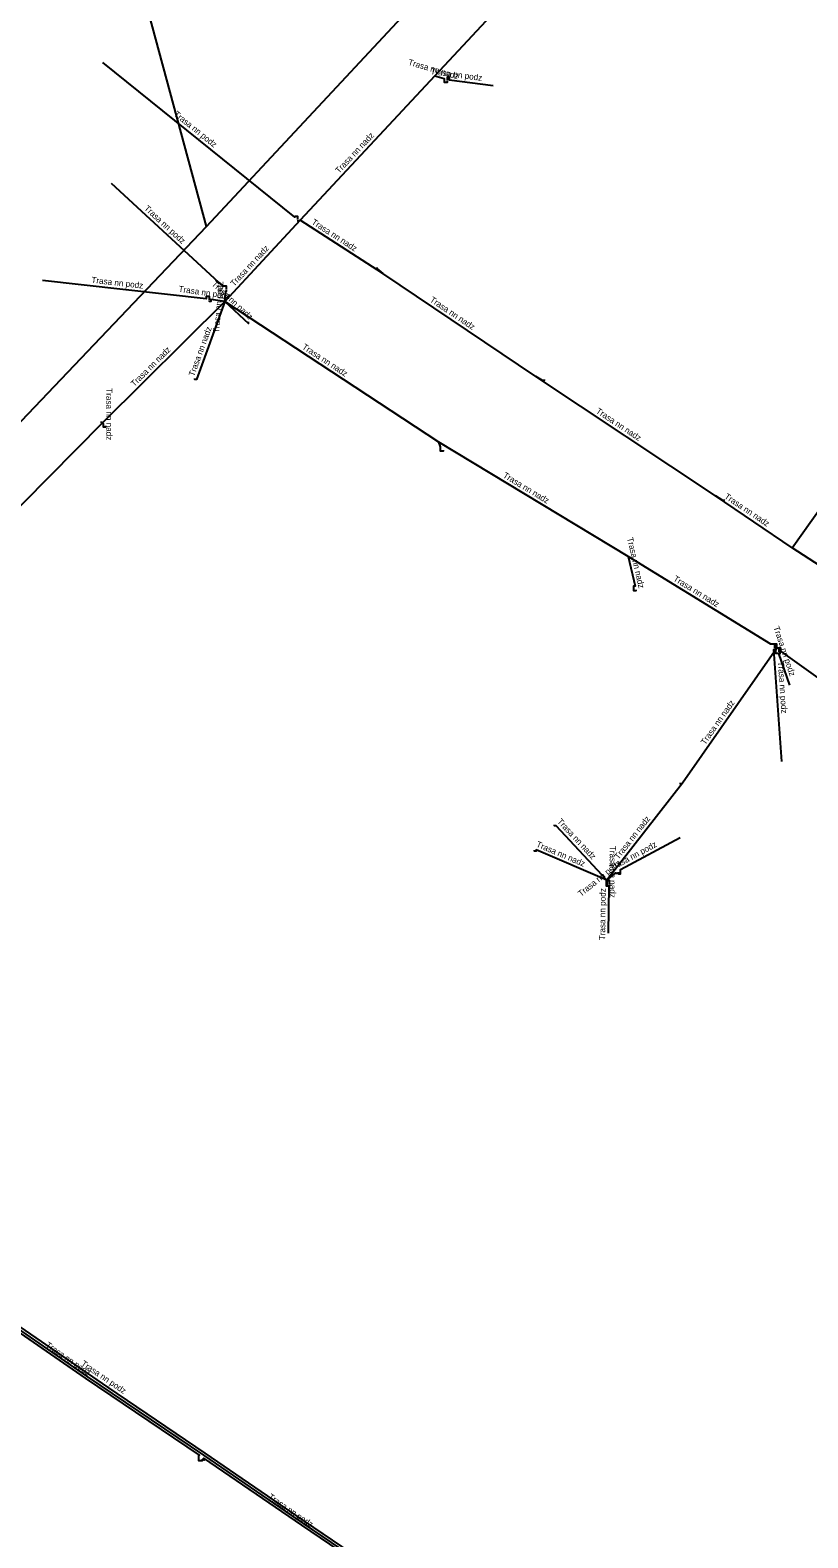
# Model space of a CAD drawing. Extents: x -742082 to -717476, y -1040737 to -1024597.
# Drawn here: x -736402.1 to -736274.4, y -1032679.3 to -1032431.7 of the extents above; entities that cross this region are included whole.
import ezdxf

# ---------------------------------------------------------------- set-up
doc = ezdxf.new("R2010")
doc.units = 0
for name, color, linetype in [('Level 13', 7, 'Continuous'), ('Level 14', 7, 'Continuous'), ('Level 15', 7, 'Continuous'), ('Level 20', 7, 'Continuous'), ('Level 24', 7, 'Continuous')]:
    doc.layers.add(name, color=color, linetype=linetype)

msp = doc.modelspace()

# ---------------------------------------------------------------- linework, layer by layer
at = {"layer": 'Level 13'}
for p, q in [((-736313.17, -1032415.01), (-736335.68, -1032439.22)), ((-736335.68, -1032439.22), (-736357.82, -1032462.91)), ((-736357.82, -1032462.91), (-736370.18, -1032476.28)), ((-736344.2, -1032471.7), (-736357.82, -1032462.91)), ((-736319.1, -1032488.6), (-736344.2, -1032471.7)), ((-736370.18, -1032476.28), (-736390.27, -1032496.22)), ((-736335, -1032499.4), (-736370.18, -1032476.28)), ((-736289.6, -1032508.2), (-736319.1, -1032488.6)), ((-736276.98, -1032516.71), (-736257.81, -1032489.67)), ((-736390.27, -1032496.22), (-736419.45, -1032525.69)), ((-736303.93, -1032518.14), (-736335, -1032499.4)), ((-736276.98, -1032516.71), (-736289.6, -1032508.2)), ((-736257.1, -1032529.7), (-736276.98, -1032516.71)), ((-736279.5, -1032533.2), (-736295.02, -1032555.39)), ((-736295.02, -1032555.39), (-736307.44, -1032571.28))]:
    msp.add_line(p, q, dxfattribs=at)
for points in [[(-736335.68, -1032439.22), (-736334.15, -1032439.67), (-736334.15, -1032440.26), (-736333.6, -1032440.26), (-736333.6, -1032440)], [(-736358.2, -1032462.9), (-736358.2, -1032463.06), (-736358.03, -1032463.06), (-736357.82, -1032462.91)], [(-736345.2, -1032470.7), (-736345.2, -1032470.86), (-736344.2, -1032471.7)], [(-736370.4, -1032476.1), (-736370.4, -1032476.27), (-736370.18, -1032476.28)], [(-736317.7, -1032489.1), (-736317.7, -1032489.26), (-736317.98, -1032489.26), (-736319.1, -1032488.6)], [(-736390.5, -1032496), (-736390.5, -1032496.16), (-736390.27, -1032496.22)], [(-736390.27, -1032496.22), (-736390.15, -1032496.29), (-736390.15, -1032496.86), (-736389.7, -1032496.86), (-736389.7, -1032496.7)], [(-736334.3, -1032500.7), (-736334.3, -1032500.86), (-736334.75, -1032500.86), (-736334.75, -1032500.15), (-736335, -1032499.4)], [(-736288.2, -1032508.8), (-736288.2, -1032508.96), (-736288.39, -1032508.96), (-736289.6, -1032508.2)], [(-736279.5, -1032533.2), (-736279.5, -1032532.57), (-736280.52, -1032532.57), (-736303.93, -1032518.14)], [(-736279.91, -1032533.24), (-736279.91, -1032533.4), (-736279.65, -1032533.4), (-736279.5, -1032533.2)], [(-736279.2, -1032533.9), (-736279.2, -1032534.06), (-736279.65, -1032534.06), (-736279.65, -1032533.61), (-736279.5, -1032533.2)], [(-736252.87, -1032552.27), (-736278.83, -1032533.68), (-736278.83, -1032533.2), (-736279.5, -1032533.2)], [(-736295.4, -1032555.3), (-736295.4, -1032555.46), (-736295.15, -1032555.46), (-736295.02, -1032555.39)], [(-736307.44, -1032571.28), (-736307.33, -1032571.45), (-736307.45, -1032571.45), (-736307.45, -1032572.16), (-736307, -1032572.16), (-736307, -1032572)]]:
    msp.add_lwpolyline(points, dxfattribs=at)
at = {"layer": 'Level 14'}
for points in [[(-736370.18, -1032476.28), (-736374.84, -1032489.11), (-736375.1, -1032489.11), (-736375.1, -1032488.9)], [(-736370.18, -1032476.28), (-736366.3, -1032479.88), (-736366.3, -1032479.6)], [(-736303.93, -1032518.14), (-736302.78, -1032523.05), (-736303.05, -1032523.05), (-736303.05, -1032523.76), (-736302.6, -1032523.76), (-736302.6, -1032523.6)], [(-736307.44, -1032571.28), (-736315.77, -1032562.36), (-736316, -1032562.36), (-736316, -1032562.2)], [(-736307.44, -1032571.28), (-736319.05, -1032566.35), (-736319.05, -1032566.56), (-736319.3, -1032566.56), (-736319.3, -1032566.4)]]:
    msp.add_lwpolyline(points, dxfattribs=at)
at = {"layer": 'Level 15'}
for points in [[(-736358.2, -1032462.79), (-736358.2, -1032462.34), (-736358.65, -1032462.34), (-736358.65, -1032462.42), (-736390.2, -1032437)], [(-736333.6, -1032439.89), (-736333.6, -1032439.45), (-736333.34, -1032439.45), (-736333.34, -1032439.85), (-736326.1, -1032440.8)], [(-736369.9, -1032474.29), (-736369.9, -1032473.75), (-736370.45, -1032473.75), (-736370.45, -1032473.79), (-736388.8, -1032456.9)], [(-736372.7, -1032475.99), (-736372.7, -1032475.45), (-736373.25, -1032475.45), (-736373.25, -1032475.85), (-736400.1, -1032472.8)], [(-736370.18, -1032476.28), (-736372.45, -1032475.95), (-736372.45, -1032476.26), (-736372.7, -1032476.26), (-736372.7, -1032476.1)], [(-736370.18, -1032476.28), (-736370.03, -1032474.56), (-736369.9, -1032474.56), (-736369.9, -1032474.4)], [(-736278.7, -1032551.8), (-736279.98, -1032533.4), (-736279.65, -1032533.4), (-736279.65, -1032532.69), (-736279.91, -1032532.69), (-736279.91, -1032532.74), (-736279.91, -1032533.13)], [(-736277.4, -1032539.3), (-736279.18, -1032534.06), (-736278.95, -1032534.06), (-736278.95, -1032533.35), (-736279.2, -1032533.35), (-736279.2, -1032533.79)], [(-736305.53, -1032570.01), (-736305.53, -1032570.27), (-736305.18, -1032570.27), (-736305.18, -1032569.57), (-736295.4, -1032564.3)], [(-736307.44, -1032571.28), (-736305.98, -1032570.1), (-736305.98, -1032570.16), (-736305.53, -1032570.16), (-736305.53, -1032570.01)], [(-736307, -1032571.89), (-736307, -1032571.35), (-736307.55, -1032571.35), (-736307.55, -1032572.26), (-736307.11, -1032572.26), (-736307.2, -1032580)], [(-736342.82, -1032687.29), (-736342.82, -1032687.66), (-736343.44, -1032687.66), (-736343.44, -1032686.76), (-736343.21, -1032686.76), (-736343.43, -1032686.32), (-736357.24, -1032676.96), (-736373.64, -1032665.72), (-736392.81, -1032652.75), (-736415.84, -1032636.86), (-736428.42, -1032628.36), (-736439.5, -1032621.03), (-736454.26, -1032610.66), (-736468.22, -1032601.22), (-736483.87, -1032590.98), (-736484.04, -1032591.08), (-736484.04, -1032591.79), (-736484.36, -1032591.79), (-736484.36, -1032591.42)], [(-736373.89, -1032666.39), (-736373.89, -1032666.65), (-736374.44, -1032666.65), (-736374.44, -1032665.74), (-736374.33, -1032665.74), (-736393.03, -1032653.08), (-736415.89, -1032637.31), (-736415.9, -1032637.33), (-736415.81, -1032637.88), (-736416.16, -1032637.71)], [(-736277.76, -1032722.42), (-736277.75, -1032723.56), (-736278.2, -1032723.56), (-736278.2, -1032724.03), (-736280.53, -1032727.1), (-736281.59, -1032727.46), (-736303.99, -1032712.27), (-736316.17, -1032704.01), (-736341.58, -1032686.66), (-736342.76, -1032686.78), (-736343.11, -1032686.04), (-736357.09, -1032676.58), (-736373.42, -1032665.39), (-736389.38, -1032654.58), (-736415.62, -1032636.53)], [(-736342.8, -1032687.29), (-736342.8, -1032687.56), (-736343.34, -1032687.56), (-736343.34, -1032687.38), (-736343.74, -1032686.59), (-736357.55, -1032677.24), (-736373.63, -1032666.21), (-736373.54, -1032666.55), (-736373.89, -1032666.39)]]:
    msp.add_lwpolyline(points, dxfattribs=at)
at = {"layer": 'Level 24'}
for points in [[(-736373.18, -1032463.93), (-736397.03, -1032375.68), (-736411.65, -1032322.19), (-736422.11, -1032274.69), (-736434.74, -1032218.35), (-736447.94, -1032160.73)], [(-736373.18, -1032463.93), (-736325.06, -1032412.33), (-736264.85, -1032349.35), (-736238.49, -1032321.39)], [(-736473.84, -1032567.15), (-736418.8, -1032511.82), (-736373.18, -1032463.93)]]:
    msp.add_lwpolyline(points, dxfattribs=at)

# ---------------------------------------------------------------- texts
at = {"layer": 'Level 20'}
for s, rotation, p in [('Trasa nn nadz', 343.673, (-736340.14, -1032437.39)), ('Trasa nn podz', 352.504, (-736336.43, -1032438.94)), ('Trasa nn podz', 321.1436, (-736378.63, -1032445.68)), ('Trasa nn nadz', 46.937, (-736351.41, -1032455.32)), ('Trasa nn podz', 317.3794, (-736383.5, -1032461.1)), ('Trasa nn nadz', 327.1628, (-736356.02, -1032463.48)), ('Trasa nn nadz', 47.2479, (-736368.63, -1032473.87)), ('Trasa nn podz', 353.5217, (-736392.12, -1032473.2)), ('Trasa nn podz', 351.7477, (-736377.82, -1032474.67)), ('Trasa nn nadz', 317.1698, (-736372.41, -1032473.53)), ('Trasa nn podz', 85.0539, (-736371.13, -1032481.49)), ('Trasa nn nadz', 326.0474, (-736336.59, -1032476.22)), ('Trasa nn nadz', 70.0232, (-736375.21, -1032488.65)), ('Trasa nn nadz', 44.7853, (-736385.04, -1032490.32)), ('Trasa nn nadz', 326.6874, (-736357.57, -1032483.97)), ('Trasa nn nadz', 270, (-736389.65, -1032490.52)), ('Trasa nn nadz', 326.3997, (-736309.31, -1032494.5)), ('Trasa nn nadz', 328.9035, (-736324.59, -1032505.09)), ('Trasa nn nadz', 326.0072, (-736288.22, -1032508.52)), ('Trasa nn nadz', 283.1612, (-736304.12, -1032515.13)), ('Trasa nn nadz', 328.345, (-736296.61, -1032522.06)), ('Trasa nn podz', 288.7414, (-736280.1, -1032529.79)), ('Trasa nn podz', 273.9791, (-736279.34, -1032535.43)), ('Trasa nn nadz', 55.0305, (-736291.27, -1032549.16)), ('Trasa nn nadz', 51.988, (-736305.5, -1032567.98)), ('Trasa nn nadz', 313.0207, (-736315.66, -1032561.74)), ('Trasa nn nadz', 336.9866, (-736319.12, -1032565.78)), ('Trasa nn podz', 28.3197, (-736306.64, -1032569.79)), ('Trasa nn nadz', 270, (-736306.95, -1032565.66)), ('Trasa nn podz', 39.0479, (-736311.66, -1032574.06)), ('Trasa nn podz', 89.3013, (-736307.71, -1032581.18)), ('Trasa nn podz', 325.4087, (-736399.7, -1032647.87)), ('Trasa nn podz', 325.8822, (-736393.87, -1032650.93)), ('Trasa nn podz', 325.583, (-736363.14, -1032672.8))]:
    msp.add_text(s, height=1, rotation=rotation, dxfattribs=at).set_placement(p)

doc.saveas('drawing.dxf')
